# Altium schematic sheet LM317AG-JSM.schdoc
size 127 x 101 mm
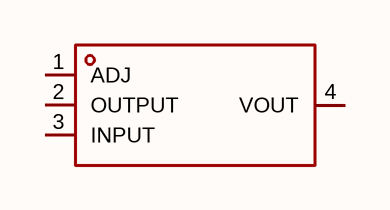
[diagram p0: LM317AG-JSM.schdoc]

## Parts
U?  lm317ag-jsm  [SOT-223_L6.3-W3.5-P2.30-LS7.0-BR]  (value not drawn)

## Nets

Not connected (* = marked no-connect by the designer): U? 1(ADJ) 2(OUTPUT) 3(INPUT) 4(VOUT)

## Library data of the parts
U? = lm317ag-jsm: 输出极性:正极;输出电压:1.25V~32V;输出电流:1.5A;电源纹波抑制比(PSRR):75dB@(120Hz);输出类型:可调;; Manufacturer: JSMSEMI(杰盛微); AddInBom: yes; ModelId: 925194bf9823436183a3e0b978a8d076; ModelName: SOT-223-4P_L6.5-W3.5-H1.6-LS7.0-P2.30; ModelTransform: 279.89794,255.905,0,180,0,0,0.0005,0.0005,0; Output Configuration: 正极; Output Current: 1.5A; Output Type: 可调; Number of Outputs: 1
